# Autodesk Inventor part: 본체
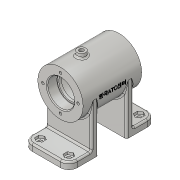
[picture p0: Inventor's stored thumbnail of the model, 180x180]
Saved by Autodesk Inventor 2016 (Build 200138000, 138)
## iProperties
Created: 2017-02
Part Number: 본체
Material: 알루미늄 6061
Document SubType Name: Modeling
Designer: H
Density: 2.7 g/cm^3
Appearance: 알루미늄 - 평지
Mass: 354.698 g
Surface Area: 422.999 cm^2
Volume: 131.37 cm^3
Author: H
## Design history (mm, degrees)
sketch "스케치2"
  geometry: C1 r 27 at (0, 0); 1 further point
  constraints: 1 centre point, 1 coincident
  dimensions: "d0" = 54 diameter of C1
extrude "돌출1" new body sketch "스케치2" stored distance "d1" = 70; taper "d2" = 0 deg
sketch "스케치4"
  geometry: L1 (-27, -35)-(27, -35) reference; L2 (27, 35)-(-27, 35) reference; L3 (0, 0)-(-60, 0); L4 (-60, 0)-(-60, 52); L5 (-60, 52)-(-52, 52); L6 (-52, 52)-(-52, 17); L7 (-52, 17)-(-60, 17) reference; L8 (-60, 17)-(-60, 52); L9 (27, -35)-(27, 35) reference; L10 (-60, -52)-(-52, -52); L11 (-52, -52)-(-52, -17); L12 (-52, -17)-(-60, -17); L13 (-60, -17)-(-60, -52)
  constraints: 20 end point, 4 symmetric about line, 3 horizontal, 2 vertical, 1 collinear, 1 perpendicular, 1 point on line
  dimensions: "d11" = 60 distance of L3.start L3.end; "d12" = 52 distance of L3.end L4.end; "d13" = 8 distance of L4.end L5.end
extrude "돌출2" join sketch "스케치4" stored distance "d17" = 54; taper "d18" = 0 deg
sketch "스케치7"
  geometry: L1 (20.591, 15)-(32, 15); L2 (32, 15)-(32, 10); L3 (32, 10)-(27, 10); L4 (-27, -35)-(27, -35) reference; L5 (27, 35)-(-27, 35) reference; L6 (27, -35)-(27, 35) reference; L7 (20.591, 15)-(20.591, 10); L8 (27, 10)-(20.591, 10); 2 further points
  constraints: 10 end point, 2 perpendicular, 1 horizontal, 1 vertical
  dimensions: "d27" = 25 vertical distance of L2.end point (27, 35); "d28" = 5 distance from line of L6 L2.end; "d108" = 25 vertical distance of point (27, 35) L7.end; "d109" = 20 vertical distance of point (27, 35) L1.end; "d110" = 11.40892 distance between parallel lines of L7 L2
revolve "회전1" sketch "스케치7" stored, may be unused: angle "d31" = 90 deg
sketch "스케치8"
  geometry: L1 (-52, -52)-(-52, -60) reference; L2 (-52, -60)-(-17, -60) reference; L3 (-17, -60)-(-17, -52) reference; L4 (-17, -52)-(-52, -52) reference; L5 (-17, -52)-(-25, -52); L6 (-17, -52)-(-17, 0); L7 (-17, 0)-(-25, 0); L8 (-25, 0)-(-25, -52); 1 further point
  constraints: 8 end point, 1 collinear, 1 horizontal, 1 perpendicular, 1 point on line, 1 vertical
  dimensions: "d33" = 8 distance of L6.end L7.end; "d36" = 52 distance of L3.end L6.end
extrude "돌출3" join sketch "스케치8" distance "d34" = 54; taper "d35" = 0 deg
sketch "스케치10"
  geometry: C1 r 16 at (0, 0); 1 further point
  constraints: 1 centre point, 1 coincident
  dimensions: "d37" = 32 diameter of C1
extrude "돌출4" cut sketch "스케치10" distance "d38" = 12; taper "d39" = 0 deg
sketch "스케치11"
  geometry: C1 r 14 at (0, 0); 1 further point
  constraints: 1 centre point, 1 coincident
  dimensions: "d40" = 28 diameter of C1
extrude "돌출5" cut sketch "스케치11" distance "d41" = 3; taper "d42" = 0 deg
sketch "스케치15" dims "d52" = 42
  geometry: 3 further points
  constraints: 1 coincident, 1 vertical alignment, 2 other
hole "구멍1" sketch "스케치15" at (0, 21) diameter "d53" = 3.242; stored, may be unused: countersink angle "d57" = 90 deg, drill point angle "d59" = 118 deg; dims "d54" = 8, "d55" = 4, "d56" = 2, "d58" = 10
sketch "스케치17"
  geometry: C1 r 5 at (0, 0) reference; 2 further points
  constraints: 1 coincident
hole "구멍2" sketch "스케치17" at (0, 0) diameter "d63" = 5.188; stored, may be unused: countersink angle "d67" = 90 deg, drill point angle "d69" = 118 deg; dims "d64" = 20, "d65" = 4, "d66" = 2, "d68" = 20
sketch "스케치18"
  geometry: L1 (0, 0)-(-18.991, -29.244); L2 (0, 0)-(0, -30.49); L3 (0, 0)-(-5.032, 3.268); L4 (-5.032, 3.268)-(-21.371, -21.892); L5 (-21.371, -21.892)-(-16.339, -25.16); C1 r 1.621 at (-21, 0) reference; C2 r 1.621 at (0, -21) reference; C3 r 1.621 at (21, 0) reference; C4 r 1.621 at (0, 21) reference; C5 r 16 at (0, 0) reference; C6 r 27 at (0, 0) reference; 1 further point
  constraints: 10 end point, 2 perpendicular, 1 point on line, 1 vertical
  dimensions: "d70" = 33 deg angle of L2 L1; "d71" = 30 distance of L3.end L4.end; "d72" = 12 diameter of L4.end L1; "d73" = 12 diameter of L3.end L1
revolve "회전2" sketch "스케치18" stored, may be unused: angle "d74" = 90 deg
sketch "스케치19"
  geometry: C1 r 22 at (0, 0); 1 further point
  constraints: 1 centre point, 1 coincident
  dimensions: "d75" = 44 diameter of C1
extrude "돌출9" cut sketch "스케치19" distance "d76" = 40; taper "d77" = 0 deg
sketch "스케치20"
  geometry: 2 further points
  constraints: 1 coincident
hole "구멍3" sketch "스케치20" at (0, 0) diameter "d78" = 5.188; stored, may be unused: countersink angle "d82" = 90 deg, drill point angle "d84" = 118 deg; dims "d79" = 20, "d80" = 4, "d81" = 2, "d83" = 20
fillet "모깎기1" dims "d85" = 10
sketch "스케치22" dims "d86" = 9
  geometry: L1 (44, 27)-(10, 27) reference; L2 (54, -8)-(54, 17) reference; L3 (0, -8)-(54, -8) reference; L4 (0, 17)-(0, -8) reference; L5 (0, -42)-(0, -67) reference; L6 (54, -42)-(0, -42) reference; L7 (54, -67)-(54, -42) reference; L8 (10, -77)-(44, -77) reference; L9 (5.5, 19.598)-(10, 22.196); L10 (10, 22.196)-(14.5, 19.598); L11 (14.5, 19.598)-(14.5, 14.402); L12 (14.5, 14.402)-(10, 11.804); L13 (10, 11.804)-(5.5, 14.402); L14 (5.5, 14.402)-(5.5, 19.598); A1 r 10 centre (10, 17) between (10, 27) and (0, 17) reference; A2 r 10 centre (44, 17) between (54, 17) and (44, 27) reference; A3 r 10 centre (10, -67) between (0, -67) and (10, -77) reference; A4 r 10 centre (44, -67) between (44, -77) and (54, -67) reference; 4 further points
  constraints: 12 end point, 2 coincident, 1 horizontal alignment, 1 midpoint, 1 vertical alignment, 15 other
extrude "돌출10" cut sketch "스케치22" distance "d87" = 3; taper "d88" = 0 deg
sketch "스케치23"
  geometry: L1 (44, 27)-(10, 27) reference; L2 (54, -8)-(54, 17) reference; L3 (0, -8)-(54, -8) reference; L4 (0, 17)-(0, -8) reference; C1 r 2.5 at (10, 17); A1 r 10 centre (10, 17) between (10, 27) and (0, 17) reference; A2 r 10 centre (44, 17) between (54, 17) and (44, 27) reference; 1 further point
  constraints: 1 centre point, 1 coincident
  dimensions: "d89" = 5 diameter of C1
extrude "돌출11" cut sketch "스케치23" stored distance "d90" = 3; taper "d91" = 0 deg
fillet "모깎기2" dims "d92" = 2
fillet "모깎기4" dims "d94" = 2
fillet "모깎기5" dims "d95" = 2
chamfer "모따기1" distance "d96" = 1; stored, may be unused: second distance "d97" = 2, angle "d98" = 45 deg
fillet "모깎기6" dims "d99" = 0.3
fillet "모깎기7" dims "d100" = 3
node "작업 평면1"
sketch "스케치24"
  geometry: L1 (27, -35)-(27, 35) reference; 2 further points
  constraints: 1 other
  dimensions: "d102" = 27 distance from line of L1 point (0, 0); "d103" = 0 distance of point (0, 0) point (0, 0)
feature "엠보싱1" sketch "스케치24" dims "d0" = 54, "d104" = 0.5, "d105" = 0
fillet "모깎기8" dims "d106" = 2
fillet "모깎기9" dims "d107" = 2
fillet "모깎기10" dims "d111" = 2
node "솔리드1"
mirror "대칭1"
pattern_circular "원형 패턴1" dims angle "d61" = 360 deg
mirror "대칭3"
mirror "대칭4"
mirror "대칭5"
mirror "대칭6"
node "투영된 루프2"
node "투영된 루프5"
node "투영된 루프6"
node "투영된 루프7"
node "투영된 루프8"
node "투영된 루프9"
node "투영된 루프10"
other parameters: "d101" = 50.75
